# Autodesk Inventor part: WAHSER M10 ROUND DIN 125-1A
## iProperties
IsCustomPart: 1
Created: 2006-02
Part Number: WAHSER M10 ROUND DIN 125-1A
Material: Steel, Mild
Description: Washer
Document SubType Name: Modeling
Standard: DIN 125
Designer: Andy Moles
Standards Organization: DIN
Language: en-US
Size Designation: A 10.5
Categories: <MemberInstance><Categories><Category DisplayName="Fasteners" InternalName="e4da775c-781d-43d5-af7c-5136215cf5a6" Mnemonic="FSTN"><Category DisplayName="Washers
Density: 1 g/cm^3
Author: Andy Moles
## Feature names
1. Body [Extrusion]
